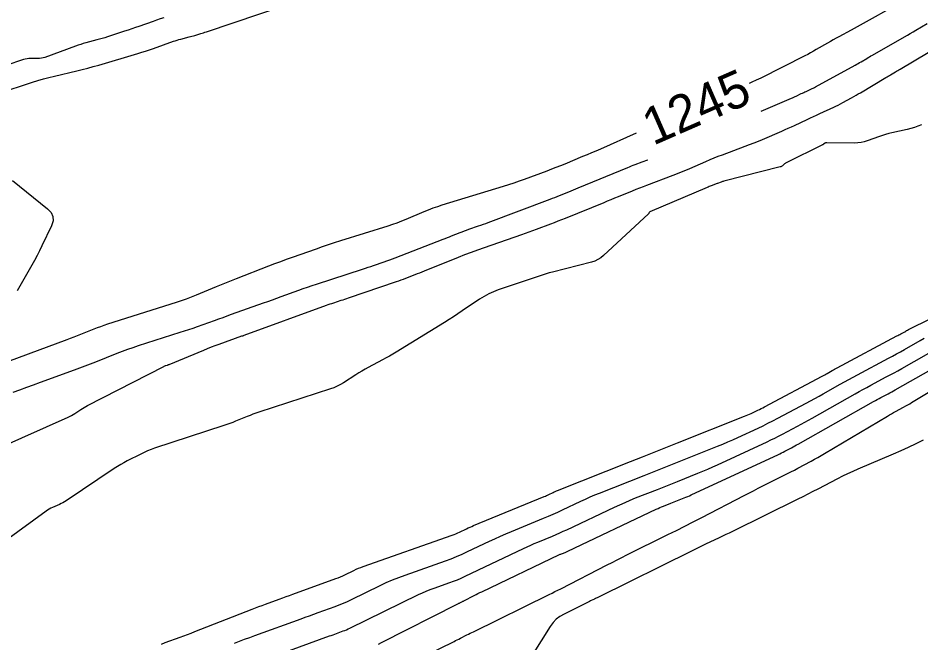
# Model space of a CAD drawing. Extents: x 658976 to 668726, y 639543 to 647196.
# Drawn here: x 662536.9 to 662683.2, y 642058.9 to 642160.2 of the extents above; entities that cross this region are included whole.
import ezdxf

# ---------------------------------------------------------------- set-up
doc = ezdxf.new("R2010")
doc.units = 0
for name, color, linetype in [('Ex_Contour Labels', 7, 'Continuous'), ('Ex_Major Contours', 7, 'Continuous'), ('Ex_Minor Contours', 7, 'Continuous')]:
    doc.layers.add(name, color=color, linetype=linetype)

msp = doc.modelspace()

# ---------------------------------------------------------------- linework, layer by layer
at = {"layer": 'Ex_Major Contours'}
for points in [[(662684.3, 642165.16), (662673.81, 642159.29), (662673.32, 642159.02), (662672.84, 642158.75), (662672.36, 642158.49), (662671.88, 642158.22), (662669.91, 642157.14), (662669.45, 642156.88), (662668.99, 642156.62), (662668.53, 642156.36), (662668.07, 642156.1), (662666.23, 642155.05), (662665.77, 642154.79), (662665.31, 642154.53), (662664.84, 642154.28), (662664.37, 642154.04), (662657.23, 642150.44), (662656.51, 642150.09), (662655.79, 642149.75), (662655.36, 642149.55)], [(662533.59, 642147.92), (662539.18, 642149.75), (662540.06, 642150.03), (662540.95, 642150.29), (662541.85, 642150.53), (662542.75, 642150.75), (662546.36, 642151.59), (662547.26, 642151.81), (662548.16, 642152.04), (662549.05, 642152.29), (662549.94, 642152.54), (662556.24, 642154.42), (662556.89, 642154.62), (662557.53, 642154.82), (662558.17, 642155.03), (662558.81, 642155.25), (662562.05, 642156.39), (662562.34, 642156.49), (662562.64, 642156.58), (662562.93, 642156.67), (662563.23, 642156.75), (662564.56, 642157.09), (662564.8, 642157.15), (662565.04, 642157.22), (662565.27, 642157.28), (662565.51, 642157.35), (662566.45, 642157.63), (662566.69, 642157.7), (662566.92, 642157.78), (662567.15, 642157.85), (662567.39, 642157.93), (662584.51, 642163.75)], [(662637.04, 642141.53), (662631.24, 642138.94), (662630.52, 642138.62), (662629.8, 642138.31), (662629.09, 642138.01), (662628.36, 642137.71), (662625.47, 642136.51), (662624.75, 642136.22), (662624.02, 642135.93), (662623.29, 642135.65), (662622.56, 642135.37), (662618.9, 642134.02), (662618.05, 642133.71), (662617.19, 642133.41), (662616.32, 642133.13), (662615.46, 642132.86), (662605.56, 642129.84), (662604.81, 642129.6), (662604.07, 642129.34), (662603.34, 642129.06), (662602.61, 642128.77), (662599.72, 642127.53), (662598.99, 642127.23), (662598.26, 642126.95), (662597.52, 642126.69), (662596.77, 642126.45), (662589.09, 642124.04), (662588.11, 642123.73), (662587.13, 642123.41), (662586.16, 642123.08), (662585.19, 642122.74), (662581.3, 642121.39), (662580.33, 642121.04), (662579.37, 642120.69), (662578.4, 642120.33), (662577.44, 642119.96), (662572.2, 642117.9), (662571.38, 642117.58), (662570.58, 642117.25), (662569.77, 642116.92), (662568.96, 642116.59), (662565.74, 642115.26), (662564.93, 642114.94), (662564.11, 642114.63), (662563.29, 642114.34), (662562.46, 642114.07), (662551.33, 642110.54), (662550.77, 642110.36), (662550.22, 642110.16), (662549.67, 642109.96), (662549.13, 642109.75), (662546.96, 642108.88), (662546.41, 642108.67), (662545.87, 642108.45), (662545.32, 642108.25), (662544.77, 642108.04), (662532.15, 642103.4)], [(662571.94, 642058.88), (662572.76, 642059.2), (662573.58, 642059.51), (662574.4, 642059.82), (662575.23, 642060.12), (662582.72, 642062.84), (662583.41, 642063.09), (662584.1, 642063.34), (662584.78, 642063.59), (662585.47, 642063.84), (662588.23, 642064.83), (662588.91, 642065.09), (662589.59, 642065.37), (662590.26, 642065.66), (662590.92, 642065.98), (662595.53, 642068.23), (662596.52, 642068.69), (662597.53, 642069.13), (662598.55, 642069.54), (662599.58, 642069.92), (662606.11, 642072.22), (662607.03, 642072.56), (662607.94, 642072.92), (662608.83, 642073.3), (662609.72, 642073.71), (662613.25, 642075.4), (662614.14, 642075.81), (662615.03, 642076.21), (662615.93, 642076.61), (662616.83, 642076.98), (662622.04, 642079.13), (662622.81, 642079.45), (662623.57, 642079.78), (662624.32, 642080.12), (662625.07, 642080.47), (662628.07, 642081.89), (662628.83, 642082.24), (662629.59, 642082.57), (662630.35, 642082.9), (662631.12, 642083.21), (662638.31, 642086.05), (662639.67, 642086.59), (662641.03, 642087.13), (662642.39, 642087.67), (662643.75, 642088.21), (662650.24, 642090.8), (662651.07, 642091.14), (662651.89, 642091.49), (662652.72, 642091.85), (662653.53, 642092.22), (662656.79, 642093.73), (662657.6, 642094.11), (662658.4, 642094.5), (662659.2, 642094.91), (662660, 642095.32), (662664.59, 642097.78), (662665.29, 642098.15), (662665.98, 642098.53), (662666.68, 642098.91), (662667.37, 642099.3), (662670.12, 642100.85), (662670.81, 642101.24), (662671.5, 642101.62), (662672.2, 642102), (662672.89, 642102.37), (662677.93, 642105.06), (662678.58, 642105.4), (662679.23, 642105.76), (662679.88, 642106.11), (662680.52, 642106.47), (662683.09, 642107.92), (662683.74, 642108.28)]]:
    msp.add_lwpolyline(points, dxfattribs=at)
at = {"layer": 'Ex_Minor Contours'}
for points in [[(662560.46, 642160.21), (662559.88, 642160.01), (662559.3, 642159.82), (662558.73, 642159.62), (662556.43, 642158.81), (662555.86, 642158.61), (662555.28, 642158.41), (662554.71, 642158.22), (662554.13, 642158.03), (662551.33, 642157.11), (662550.9, 642156.98), (662550.47, 642156.85), (662550.04, 642156.72), (662549.6, 642156.61), (662547.86, 642156.15), (662547.43, 642156.03), (662547, 642155.9), (662546.57, 642155.76), (662546.14, 642155.61), (662541.19, 642153.79), (662540.91, 642153.7), (662540.63, 642153.64), (662540.34, 642153.6), (662540.05, 642153.59), (662538.88, 642153.6), (662538.59, 642153.59), (662538.31, 642153.56), (662538.02, 642153.5), (662537.74, 642153.42), (662534.87, 642152.49)], [(662657.32, 642145.08), (662662.19, 642147.17), (662662.39, 642147.26), (662662.59, 642147.35), (662662.79, 642147.44), (662662.99, 642147.53), (662663.8, 642147.91), (662663.99, 642148), (662664.19, 642148.09), (662664.38, 642148.18), (662664.58, 642148.27), (662665.36, 642148.63), (662665.56, 642148.72), (662665.75, 642148.82), (662665.94, 642148.92), (662666.13, 642149.02), (662672.56, 642152.55), (662672.79, 642152.68), (662673.02, 642152.81), (662673.25, 642152.94), (662673.48, 642153.08), (662674.4, 642153.63), (662674.63, 642153.76), (662674.86, 642153.9), (662675.09, 642154.03), (662675.32, 642154.16), (662680.55, 642157.13), (662681, 642157.39), (662681.46, 642157.66), (662681.91, 642157.92), (662682.37, 642158.19), (662684.18, 642159.28)], [(662533.89, 642090.6), (662544.99, 642095.51), (662545.27, 642095.64), (662545.53, 642095.78), (662545.79, 642095.93), (662546.05, 642096.09), (662547.05, 642096.76), (662547.3, 642096.92), (662547.56, 642097.08), (662547.82, 642097.23), (662548.09, 642097.37), (662560.48, 642103.73), (662560.55, 642103.77), (662560.62, 642103.8), (662560.69, 642103.82), (662560.76, 642103.85), (662561.05, 642103.94), (662561.12, 642103.97), (662561.19, 642103.99), (662561.26, 642104.02), (662561.33, 642104.05), (662566.97, 642106.38), (662567.58, 642106.63), (662568.2, 642106.87), (662568.82, 642107.11), (662569.45, 642107.33), (662573.14, 642108.65), (662573.26, 642108.69), (662573.38, 642108.73), (662573.4, 642108.74), (662573.43, 642108.75), (662573.46, 642108.76), (662573.49, 642108.78), (662586.83, 642113.62), (662587.13, 642113.73), (662587.43, 642113.84), (662587.73, 642113.94), (662588.03, 642114.04), (662589.23, 642114.43), (662589.53, 642114.53), (662589.83, 642114.63), (662590.13, 642114.73), (662590.43, 642114.83), (662598.18, 642117.47), (662598.56, 642117.6), (662598.94, 642117.74), (662599.33, 642117.88), (662599.7, 642118.02), (662601.22, 642118.61), (662601.6, 642118.75), (662601.98, 642118.9), (662602.35, 642119.05), (662602.73, 642119.2), (662608.24, 642121.43), (662609.29, 642121.84), (662610.34, 642122.24), (662611.4, 642122.63), (662612.46, 642123.01), (662618.51, 642125.1), (662619.11, 642125.31), (662619.7, 642125.52), (662620.29, 642125.74), (662620.87, 642125.96), (662623.22, 642126.84), (662623.81, 642127.06), (662624.4, 642127.29), (662624.98, 642127.52), (662625.56, 642127.75), (662631.84, 642130.3), (662632.41, 642130.53), (662632.99, 642130.77), (662633.57, 642131.01), (662634.15, 642131.24), (662636.46, 642132.19), (662637.04, 642132.43), (662637.62, 642132.66), (662638.2, 642132.88), (662638.78, 642133.11), (662643.06, 642134.71), (662643.73, 642134.96), (662644.4, 642135.23), (662645.06, 642135.5), (662645.72, 642135.79), (662648.35, 642136.94), (662649.01, 642137.22), (662649.68, 642137.5), (662650.34, 642137.76), (662651.02, 642138.02), (662654.73, 642139.39), (662655.43, 642139.66), (662656.14, 642139.93), (662656.84, 642140.22), (662657.53, 642140.51), (662660.66, 642141.85), (662661.18, 642142.08), (662661.69, 642142.31), (662662.21, 642142.54), (662662.72, 642142.77), (662664.78, 642143.74), (662665.29, 642143.97), (662665.79, 642144.2), (662666.29, 642144.44), (662666.79, 642144.67), (662669.05, 642145.72), (662669.42, 642145.89), (662669.79, 642146.07), (662670.16, 642146.26), (662670.52, 642146.46), (662671.96, 642147.25), (662672.32, 642147.45), (662672.68, 642147.65), (662673.03, 642147.86), (662673.39, 642148.07), (662677.52, 642150.54), (662677.71, 642150.65), (662677.9, 642150.76), (662678.09, 642150.87), (662678.28, 642150.98), (662679.05, 642151.42), (662679.24, 642151.53), (662679.43, 642151.64), (662679.62, 642151.75), (662679.81, 642151.86), (662688.62, 642157.13)], [(662683.26, 642142.85), (662682.7, 642142.62), (662682.14, 642142.42), (662681.56, 642142.25), (662680.98, 642142.11), (662678.48, 642141.56), (662677.97, 642141.44), (662677.46, 642141.3), (662676.96, 642141.14), (662676.47, 642140.97), (662674.49, 642140.25), (662674, 642140.1), (662673.49, 642139.99), (662672.98, 642139.92), (662672.46, 642139.91), (662667.94, 642139.97), (662667.86, 642139.97), (662667.79, 642139.95), (662667.72, 642139.93), (662667.66, 642139.89), (662667.4, 642139.72), (662667.34, 642139.68), (662667.27, 642139.64), (662667.21, 642139.6), (662667.14, 642139.57), (662661.45, 642136.75), (662661.35, 642136.7), (662661.26, 642136.65), (662661.17, 642136.58), (662661.09, 642136.52), (662660.76, 642136.24), (662660.67, 642136.17), (662660.58, 642136.12), (662660.48, 642136.08), (662660.38, 642136.05), (662651.26, 642133.72), (662651.15, 642133.69), (662651.04, 642133.66), (662650.94, 642133.62), (662650.83, 642133.59), (662650.22, 642133.36), (662650.2, 642133.35), (662650.19, 642133.34), (662650.18, 642133.34), (662649.2, 642132.98), (662649.04, 642132.91), (662648.87, 642132.85), (662648.71, 642132.78), (662648.55, 642132.71), (662639.26, 642128.77), (662639.23, 642128.75), (662639.2, 642128.73), (662639.18, 642128.7), (662639.17, 642128.67), (662639.11, 642128.54), (662639.09, 642128.5), (662639.07, 642128.47), (662639.05, 642128.45), (662639.03, 642128.42), (662631.76, 642121.68), (662631.32, 642121.32), (662630.85, 642121.02), (662630.34, 642120.79), (662629.79, 642120.61), (662623.45, 642119), (662622.95, 642118.87), (662622.46, 642118.73), (662621.97, 642118.58), (662621.48, 642118.42), (662614.69, 642116.11), (662613.9, 642115.82), (662613.13, 642115.46), (662612.38, 642115.06), (662611.66, 642114.61), (662608.84, 642112.7), (662608.13, 642112.23), (662607.42, 642111.76), (662606.7, 642111.3), (662605.97, 642110.85), (662598.15, 642106.05), (662597.6, 642105.72), (662597.05, 642105.4), (662596.5, 642105.09), (662595.94, 642104.78), (662593.61, 642103.55), (662593.09, 642103.26), (662592.58, 642102.97), (662592.08, 642102.67), (662591.58, 642102.35), (662589.59, 642101.08), (662589.09, 642100.77), (662588.56, 642100.51), (662588.03, 642100.27), (662587.47, 642100.07), (662575.88, 642096.3), (662575.4, 642096.14), (662574.93, 642095.97), (662574.45, 642095.79), (662573.98, 642095.6), (662572.11, 642094.83), (662571.65, 642094.64), (662571.17, 642094.46), (662570.7, 642094.29), (662570.22, 642094.13), (662558.98, 642090.46), (662558.4, 642090.25), (662557.84, 642090.03), (662557.28, 642089.79), (662556.73, 642089.52), (662554.56, 642088.4), (662554.02, 642088.11), (662553.49, 642087.81), (662552.97, 642087.5), (662552.45, 642087.16), (662544.63, 642081.95), (662544.37, 642081.78), (662544.11, 642081.63), (662543.84, 642081.49), (662543.56, 642081.36), (662542.43, 642080.86), (662542.16, 642080.73), (662541.89, 642080.58), (662541.63, 642080.42), (662541.38, 642080.25), (662534.83, 642075.46)], [(662536.05, 642099.55), (662537.16, 642099.95), (662538.26, 642100.36), (662539.37, 642100.76), (662540.47, 642101.16), (662545.98, 642103.17), (662546.85, 642103.49), (662547.72, 642103.81), (662548.58, 642104.14), (662549.45, 642104.48), (662552.89, 642105.85), (662553.76, 642106.19), (662554.63, 642106.51), (662555.5, 642106.81), (662556.38, 642107.1), (662563.14, 642109.25), (662563.84, 642109.47), (662564.54, 642109.7), (662565.23, 642109.94), (662565.92, 642110.18), (662568.69, 642111.17), (662569.39, 642111.42), (662570.08, 642111.66), (662570.77, 642111.91), (662571.46, 642112.16), (662576.64, 642114), (662577.36, 642114.26), (662578.07, 642114.52), (662578.79, 642114.78), (662579.5, 642115.03), (662582.36, 642116.07), (662583.08, 642116.33), (662583.79, 642116.58), (662584.51, 642116.83), (662585.24, 642117.06), (662592.7, 642119.49), (662593.14, 642119.63), (662593.58, 642119.78), (662594.02, 642119.93), (662594.46, 642120.08), (662596.21, 642120.67), (662596.65, 642120.83), (662597.09, 642120.98), (662597.52, 642121.14), (662597.95, 642121.31), (662605.75, 642124.31), (662606.1, 642124.44), (662606.44, 642124.58), (662606.79, 642124.71), (662607.13, 642124.85), (662608.5, 642125.41), (662608.85, 642125.54), (662609.19, 642125.67), (662609.54, 642125.8), (662609.89, 642125.93), (662611.5, 642126.48), (662611.88, 642126.62), (662612.27, 642126.76), (662612.65, 642126.89), (662613.03, 642127.04), (662623.08, 642130.81), (662623.46, 642130.96), (662623.84, 642131.11), (662624.22, 642131.26), (662624.6, 642131.41), (662626.12, 642132.02), (662626.5, 642132.18), (662626.88, 642132.33), (662627.25, 642132.49), (662627.63, 642132.64), (662635.69, 642135.95), (662635.98, 642136.07), (662636.27, 642136.19), (662636.56, 642136.3), (662636.86, 642136.41), (662638.03, 642136.85), (662638.33, 642136.97), (662638.62, 642137.08), (662638.91, 642137.2), (662638.93, 642137.21)], [(662535.96, 642133.85), (662541.64, 642129.27), (662542.2, 642128.68), (662542.49, 642128.02), (662542.52, 642127.3), (662542.27, 642126.52), (662540.72, 642123.25), (662540.34, 642122.45), (662539.94, 642121.67), (662539.53, 642120.9), (662539.1, 642120.13), (662536.73, 642115.95)], [(662560.08, 642058.75), (662560.69, 642058.97), (662563.12, 642059.84), (662563.72, 642060.07), (662564.33, 642060.29), (662564.93, 642060.52), (662565.53, 642060.75), (662574.77, 642064.38), (662575.32, 642064.6), (662575.87, 642064.81), (662576.42, 642065.01), (662576.97, 642065.21), (662579.19, 642066.02), (662579.74, 642066.22), (662580.29, 642066.42), (662580.85, 642066.62), (662581.4, 642066.82), (662588.34, 642069.34), (662588.72, 642069.48), (662589.1, 642069.63), (662589.47, 642069.79), (662589.83, 642069.97), (662591.29, 642070.68), (662591.65, 642070.85), (662592.02, 642071.01), (662592.4, 642071.16), (662592.78, 642071.3), (662607.23, 642076.39), (662607.53, 642076.5), (662607.82, 642076.62), (662608.11, 642076.74), (662608.4, 642076.88), (662609.54, 642077.42), (662609.82, 642077.55), (662610.11, 642077.68), (662610.4, 642077.81), (662610.69, 642077.93), (662622.13, 642082.65), (662622.32, 642082.72), (662622.5, 642082.8), (662622.68, 642082.88), (662622.86, 642082.97), (662623.57, 642083.3), (662623.75, 642083.39), (662623.93, 642083.47), (662624.11, 642083.54), (662624.3, 642083.62), (662636.14, 642088.3), (662638.04, 642089.05), (662639.95, 642089.81), (662641.85, 642090.56), (662643.75, 642091.32), (662654.61, 642095.66), (662654.89, 642095.77), (662655.16, 642095.88), (662655.43, 642096), (662655.7, 642096.12), (662656.77, 642096.62), (662657.04, 642096.75), (662657.3, 642096.88), (662657.57, 642097.01), (662657.83, 642097.15), (662667.19, 642102.14), (662667.4, 642102.25), (662667.6, 642102.36), (662667.8, 642102.47), (662668, 642102.59), (662668.8, 642103.04), (662669, 642103.15), (662669.2, 642103.26), (662669.4, 642103.37), (662669.6, 642103.48), (662679.3, 642108.65), (662679.46, 642108.73), (662679.62, 642108.82), (662679.78, 642108.9), (662679.94, 642108.99), (662680.57, 642109.35), (662680.72, 642109.43), (662680.88, 642109.52), (662681.04, 642109.6), (662681.2, 642109.69), (662692.15, 642115.12)], [(662571.69, 642054.37), (662587.34, 642060.05), (662587.62, 642060.15), (662587.9, 642060.25), (662588.17, 642060.35), (662588.45, 642060.45), (662589.56, 642060.86), (662589.83, 642060.96), (662590.1, 642061.07), (662590.37, 642061.19), (662590.64, 642061.31), (662601.78, 642066.75), (662602.39, 642067.04), (662603.01, 642067.31), (662603.63, 642067.56), (662604.27, 642067.79), (662606.81, 642068.69), (662607.45, 642068.92), (662608.07, 642069.17), (662608.69, 642069.44), (662609.3, 642069.72), (662618.78, 642074.24), (662619.36, 642074.51), (662619.94, 642074.77), (662620.52, 642075.02), (662621.11, 642075.27), (662623.47, 642076.24), (662624.06, 642076.49), (662624.64, 642076.74), (662625.22, 642077.01), (662625.8, 642077.27), (662633.55, 642080.93), (662634.39, 642081.32), (662635.23, 642081.7), (662636.08, 642082.06), (662636.94, 642082.41), (662640.47, 642083.8), (662641.29, 642084.12), (662642.11, 642084.45), (662642.92, 642084.77), (662643.74, 642085.1), (662647.01, 642086.4), (662647.83, 642086.74), (662648.64, 642087.08), (662649.44, 642087.43), (662650.24, 642087.8), (662658.27, 642091.51), (662658.89, 642091.8), (662659.51, 642092.11), (662660.13, 642092.42), (662660.73, 642092.74), (662663.16, 642094.03), (662663.77, 642094.36), (662664.37, 642094.69), (662664.98, 642095.02), (662665.58, 642095.35), (662672.55, 642099.29), (662673.18, 642099.64), (662673.8, 642099.99), (662674.43, 642100.33), (662675.06, 642100.67), (662677.58, 642102.01), (662678.21, 642102.35), (662678.84, 642102.69), (662679.47, 642103.03), (662680.09, 642103.38), (662686.47, 642106.98)], [(662595.28, 642058.73), (662595.75, 642058.97), (662608.14, 642065.27), (662608.22, 642065.31), (662608.3, 642065.35), (662608.38, 642065.39), (662608.46, 642065.43), (662608.79, 642065.59), (662608.87, 642065.63), (662608.95, 642065.67), (662609.04, 642065.71), (662609.12, 642065.75), (662610.78, 642066.61), (662611.09, 642066.76), (662611.39, 642066.92), (662611.7, 642067.07), (662612.01, 642067.21), (662624.63, 642073.23), (662624.74, 642073.28), (662624.85, 642073.33), (662624.96, 642073.38), (662625.07, 642073.42), (662625.51, 642073.6), (662625.62, 642073.65), (662625.72, 642073.7), (662625.83, 642073.75), (662625.94, 642073.8), (662640.3, 642080.59), (662640.59, 642080.72), (662640.87, 642080.84), (662641.16, 642080.96), (662641.45, 642081.08), (662642.64, 642081.55), (662642.91, 642081.66), (662643.19, 642081.77), (662643.46, 642081.88), (662643.74, 642081.99), (662644.84, 642082.43), (662645.11, 642082.54), (662645.39, 642082.65), (662645.66, 642082.77), (662645.93, 642082.9), (662660.08, 642089.44), (662660.35, 642089.57), (662660.62, 642089.7), (662660.89, 642089.84), (662661.16, 642089.98), (662662.23, 642090.55), (662662.5, 642090.7), (662662.76, 642090.84), (662663.03, 642090.99), (662663.29, 642091.14), (662675.52, 642098.03), (662675.81, 642098.2), (662676.1, 642098.36), (662676.4, 642098.52), (662676.69, 642098.67), (662677.87, 642099.3), (662678.16, 642099.46), (662678.46, 642099.62), (662678.75, 642099.78), (662679.04, 642099.94), (662690.68, 642106.5)], [(662593.61, 642052.36), (662607.52, 642059.17), (662607.78, 642059.3), (662608.05, 642059.43), (662608.31, 642059.56), (662608.57, 642059.69), (662609.6, 642060.22), (662609.86, 642060.35), (662610.13, 642060.48), (662610.39, 642060.61), (662610.65, 642060.74), (662622.94, 642066.77), (662623.4, 642067), (662623.87, 642067.23), (662624.33, 642067.47), (662624.8, 642067.7), (662632.35, 642071.57), (662633.14, 642071.98), (662633.94, 642072.38), (662634.74, 642072.78), (662635.54, 642073.18), (662642.19, 642076.47), (662643.56, 642077.16), (662644.93, 642077.85), (662646.3, 642078.54), (662647.66, 642079.25), (662654.54, 642082.82), (662655.29, 642083.21), (662656.05, 642083.59), (662656.81, 642083.98), (662657.57, 642084.36), (662661.03, 642086.08), (662661.58, 642086.36), (662662.13, 642086.64), (662662.68, 642086.93), (662663.22, 642087.22), (662665.41, 642088.39), (662665.95, 642088.69), (662666.49, 642088.99), (662667.03, 642089.3), (662667.56, 642089.61), (662677.78, 642095.68), (662678.11, 642095.87), (662678.43, 642096.05), (662678.75, 642096.24), (662679.08, 642096.42), (662680.39, 642097.13), (662680.72, 642097.31), (662681.05, 642097.49), (662681.37, 642097.68), (662681.69, 642097.87), (662694.62, 642105.63)], [(662683.55, 642091.79), (662682.36, 642091.17), (662681.15, 642090.58), (662679.93, 642090.02), (662678.7, 642089.49), (662672.96, 642087.06), (662672.13, 642086.7), (662671.3, 642086.32), (662670.49, 642085.93), (662669.68, 642085.52), (662666.46, 642083.84), (662665.66, 642083.43), (662664.85, 642083.02), (662664.04, 642082.61), (662663.23, 642082.21), (662652.63, 642077), (662652.09, 642076.73), (662651.55, 642076.47), (662651.01, 642076.21), (662650.47, 642075.95), (662648.3, 642074.92), (662647.75, 642074.66), (662647.21, 642074.4), (662646.67, 642074.14), (662646.13, 642073.87), (662630.82, 642066.3), (662630.69, 642066.23), (662630.56, 642066.17), (662630.42, 642066.11), (662630.29, 642066.04), (662629.76, 642065.79), (662629.63, 642065.72), (662629.49, 642065.66), (662629.36, 642065.59), (662629.23, 642065.53), (662625.34, 642063.59), (662624.68, 642063.21), (662624.09, 642062.75), (662623.57, 642062.21), (662623.12, 642061.59), (662617.52, 642052.75)]]:
    msp.add_lwpolyline(points, dxfattribs=at)

# ---------------------------------------------------------------- texts
at = {"layer": 'Ex_Contour Labels'}
msp.add_text('1245', height=6, rotation=23.6398, dxfattribs=at).set_placement((662639.77, 642139.45))

doc.saveas('drawing.dxf')
